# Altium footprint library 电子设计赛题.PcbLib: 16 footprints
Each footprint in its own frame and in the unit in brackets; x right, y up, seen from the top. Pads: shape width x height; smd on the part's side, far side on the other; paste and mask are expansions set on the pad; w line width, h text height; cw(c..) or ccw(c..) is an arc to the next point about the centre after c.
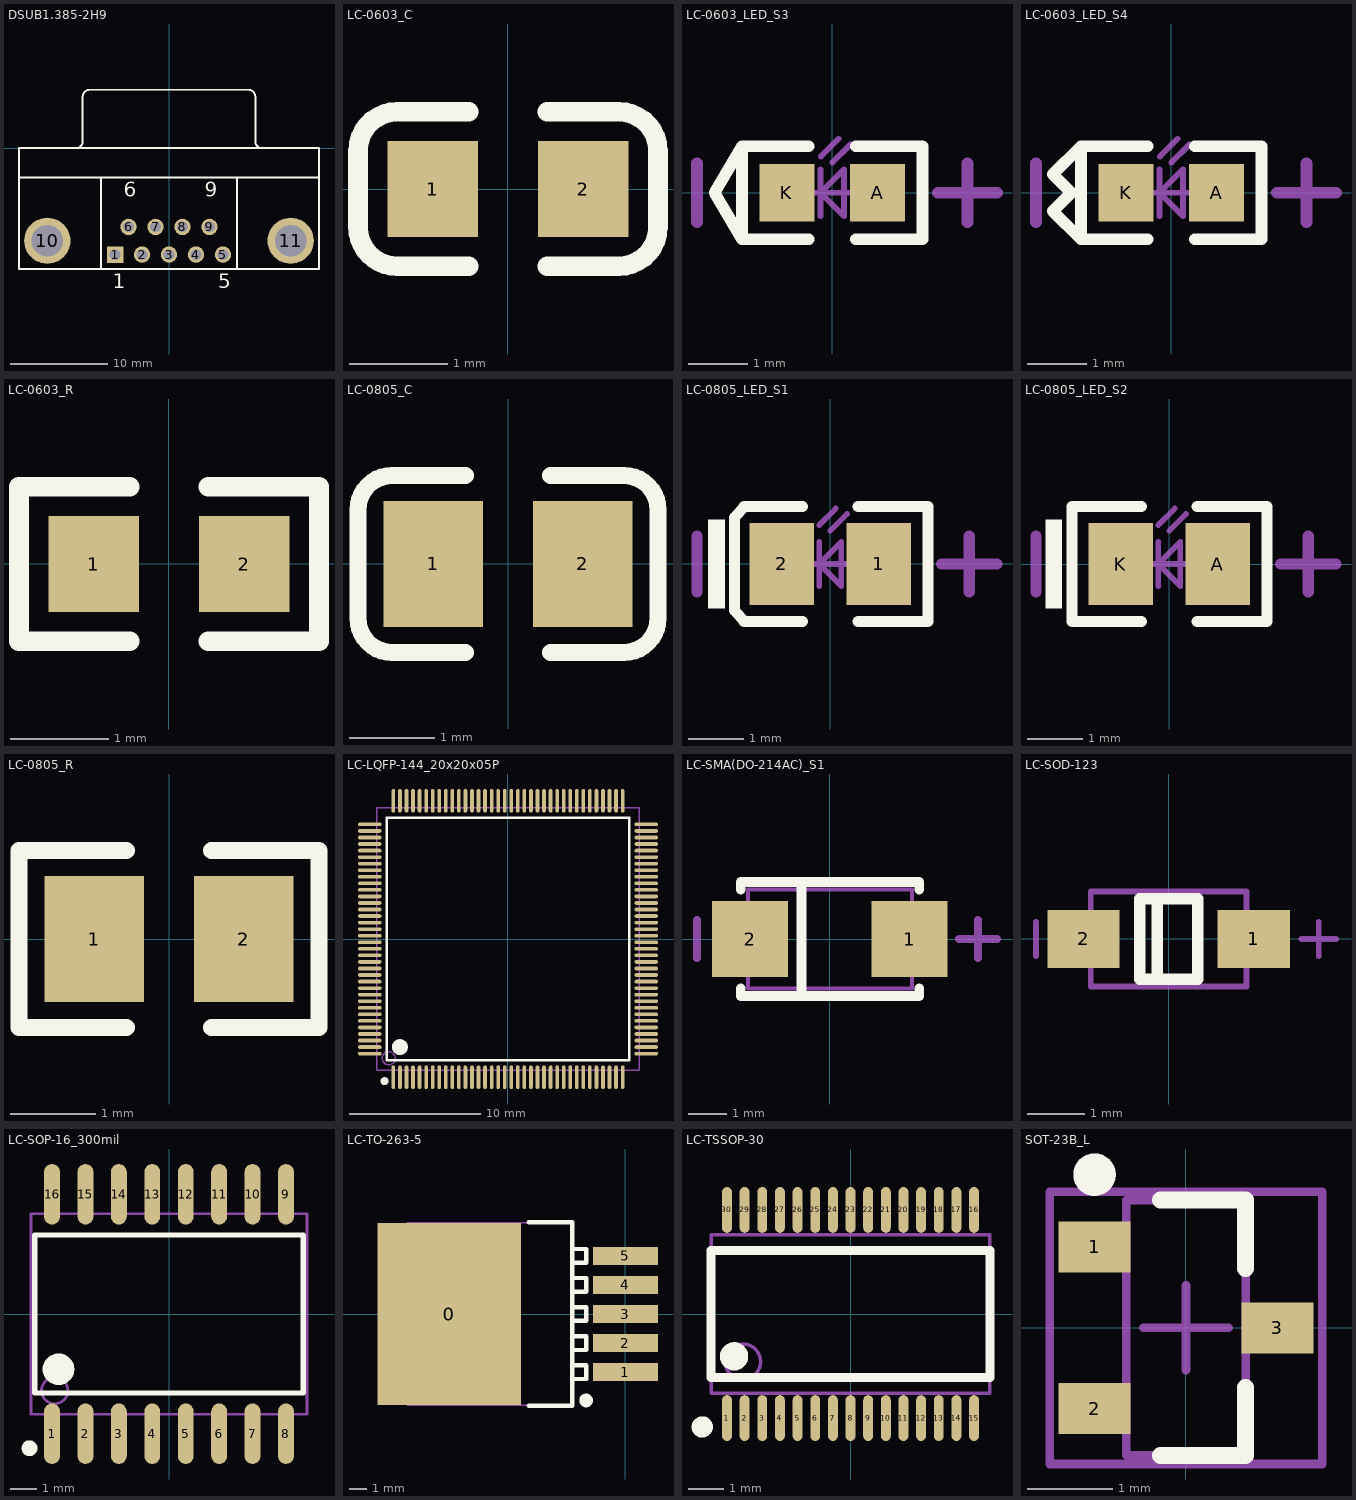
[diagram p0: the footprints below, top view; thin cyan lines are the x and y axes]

## DSUB1.385-2H9 [mm] "Connector; D Subminiature; 9 Position; Right Angle; Pitch 1.385 mm"
height 12.75
pads (11):
  rect 1.69x1.69 hole 1.09: 1(-5.54,-10.92)
  round 1.69 hole 1.09: 2(-2.77,-10.92) 3(0,-10.92) 4(2.77,-10.92) 5(5.54,-10.92) 6(-4.155,-8.08) 7(-1.385,-8.08) 8(1.385,-8.08) 9(4.155,-8.08)
  round 4.76 hole 3.26: 10(-12.495,-9.5) 11(12.495,-9.5)
Top Overlay:
  lines w0.2: -15.4,-3 15.4,-3 ; -9.56,0.005 ccw(c-9.56,0.7) -8.865,0.7 -8.865,5.3 ; -8.86,5.305 cw(c-8.165,5.305) -8.165,6 8.165,6 cw(c8.165,5.305) 8.86,5.305 ; -7,-12.4 -7,-3 ; 7,-12.4 7,-3 ; 8.865,5.3 8.865,0.7 ccw(c9.56,0.7) 9.56,0.005 ; -15.4,-12.4 15.4,-12.4 15.4,0 -15.4,0 -15.4,-12.4
  text "6" at -4.655,-4.975 h1.5
  text "9" at 3.655,-4.975 h1.5
  text "5" at 5.04,-14.375 h1.5
  text "1" at -5.79,-14.375 h1.5

## LC-0603_C [mm]
height 1.1
pads (2):
  rect 0.93x0.98 smd: 1(-0.77,0) 2(0.77,0)
Top Overlay:
  lines w0.2: -0.4,-0.79 -1.135,-0.79 cw(c-1.135,-0.39) -1.535,-0.39 -1.535,0.39 cw(c-1.135,0.39) -1.135,0.79 -0.4,0.79 ; 0.4,-0.79 1.135,-0.79 ccw(c1.135,-0.39) 1.535,-0.39 1.535,0.39 ccw(c1.135,0.39) 1.135,0.79 0.4,0.79
3D body "User Library-0603 SMD Capacitor.STEP": height 0.3, standoff 0, extent -0.8,-0.4 0.8,0.4

## LC-0603_LED_S3 [mm]
height 1.1
pads (2):
  rect 0.93x0.98 smd: A(0.77,0) K(-0.77,0)
Top Overlay:
  lines w0.2: -0.4,-0.79 -1.535,-0.79 ; -0.4,0.79 -1.535,0.79 ; 0.4,-0.79 1.535,-0.79 1.535,0.79 0.4,0.79 ; -1.535,-0.79 -2,0 -1.535,0.79 ; -1.535,-0.79 -1.535,0.79
Mechanical 13:
  lines w0.1: -0.4,0 0.4,0 ; -0.2,-0.4 -0.2,0.4 ; -0.195,0.617 0.105,0.917 ; 0.005,0.517 0.305,0.817 ; -0.2,0 0.2,0.4 0.2,-0.4 -0.2,0
Mechanical 15:
  lines w0.203: -2.3,-0.5 -2.3,0.5 ; 1.8,0 2.8,0 ; 2.3,-0.5 2.3,0.5
3D body "User Library-LED_0603_R.STEP": height 0.6, standoff 0, extent -0.8,-0.4 0.8,0.4

## LC-0603_LED_S4 [mm]
height 1.1
pads (2):
  rect 0.93x0.98 smd: A(0.77,0) K(-0.77,0)
Top Overlay:
  lines w0.2: -0.4,-0.79 -1.535,-0.79 ; -0.4,0.79 -1.535,0.79 ; 0.4,-0.79 1.535,-0.79 1.535,0.79 0.4,0.79 ; -1.535,-0.79 -2.012,-0.313 -1.7,0 -2.012,0.313 -1.535,0.79 ; -1.535,-0.79 -1.535,0.79
Mechanical 13:
  lines w0.1: -0.4,0 0.4,0 ; -0.2,-0.4 -0.2,0.4 ; -0.195,0.617 0.105,0.917 ; 0.005,0.517 0.305,0.817 ; -0.2,0 0.2,-0.4 0.2,0.4 -0.2,0
Mechanical 15:
  lines w0.203: -2.3,-0.5 -2.3,0.5 ; 1.8,0 2.8,0 ; 2.3,-0.5 2.3,0.5
3D body "User Library-LED_0603_R.STEP": height 0.6, standoff 0, extent -0.8,-0.4 0.8,0.4

## LC-0603_R [mm]
height 1.1
pads (2):
  rect 0.93x0.98 smd: 1(-0.77,0) 2(0.77,0)
Top Overlay:
  lines w0.2: -0.4,-0.79 -1.535,-0.79 -1.535,0.79 -0.4,0.79 ; 0.4,-0.79 1.535,-0.79 1.535,0.79 0.4,0.79
3D body "User Library-RES_1609-0603.STEP": height 0.56, standoff 0, extent -0.85,-0.4 0.85,0.4

## LC-0805_C [mm]
height 1.1
pads (2):
  rect 1.16x1.47 smd: 1(-0.875,0) 2(0.875,0)
Top Overlay:
  lines w0.2: -0.5,-1.035 -1.355,-1.035 cw(c-1.355,-0.635) -1.755,-0.635 -1.755,0.635 cw(c-1.355,0.635) -1.355,1.035 -0.5,1.035 ; 0.5,-1.035 1.355,-1.035 ccw(c1.355,-0.635) 1.755,-0.635 1.755,0.635 ccw(c1.355,0.635) 1.355,1.035 0.5,1.035
3D body "User Library-0805 SMD Capacitor.STEP": height 0.77, standoff -0.01, extent -0.999,-0.625 1.001,0.625

## LC-0805_LED_S1 [mm]
height 1.1
pads (2):
  rect 1.16x1.47 smd: 1(0.875,0) 2(-0.875,0)
Top Overlay:
  rectangle: -2.2,-0.8 -1.9,0.8
  lines w0.2: -0.5,-1.035 -1.55,-1.035 -1.725,-0.835 -1.725,0.835 -1.55,1.035 -0.5,1.035 ; 0.5,-1.035 1.755,-1.035 1.755,1.035 0.5,1.035
Mechanical 13:
  lines w0.1: -0.4,0 0.4,0 ; -0.2,-0.4 -0.2,0.4 ; -0.2,0.7 0.1,1 ; 0,0.6 0.3,0.9 ; -0.2,0 0.2,-0.4 0.2,0.4 -0.2,0
Mechanical 15:
  lines w0.203: -2.4,-0.5 -2.4,0.5 ; 2,0 3,0 ; 2.5,-0.5 2.5,0.5
3D body "User Library-led_0805.step": height 1.1, standoff 0, extent -1.01,-0.625 1.01,0.625

## LC-0805_LED_S2 [mm]
height 1.1
pads (2):
  rect 1.16x1.47 smd: A(0.875,0) K(-0.875,0)
Top Overlay:
  rectangle: -2.23,-0.8 -1.93,0.8
  lines w0.2: -0.5,-1.035 -1.755,-1.035 -1.755,1.035 -0.5,1.035 ; 0.5,-1.035 1.755,-1.035 1.755,1.035 0.5,1.035
Mechanical 13:
  lines w0.1: -0.4,0 0.4,0 ; -0.2,-0.4 -0.2,0.4 ; -0.2,0.7 0.1,1 ; 0,0.6 0.3,0.9 ; -0.2,0 0.2,-0.4 0.2,0.4 -0.2,0
Mechanical 15:
  lines w0.203: -2.4,-0.5 -2.4,0.5 ; 2,0 3,0 ; 2.5,-0.5 2.5,0.5
3D body "User Library-led_0805.step": height 1.1, standoff 0, extent -1.01,-0.625 1.01,0.625

## LC-0805_R [mm]
height 1.1
pads (2):
  rect 1.16x1.47 smd: 1(-0.875,0) 2(0.875,0)
Top Overlay:
  lines w0.2: -0.5,-1.035 -1.755,-1.035 -1.755,1.035 -0.5,1.035 ; 0.5,-1.035 1.755,-1.035 1.755,1.035 0.5,1.035
3D body "User Library-R_0805.STEP": height 0.49, standoff -0.01, extent -0.997,-0.625 1.003,0.625

## LC-LQFP-144_20x20x05P [mm]
height 1.1
pads (144):
  oval 0.28x1.8 smd mask+0.051: 1(-8.75,-10.55) 2(-8.25,-10.55) 3(-7.75,-10.55) 4(-7.25,-10.55) 5(-6.75,-10.55) 6(-6.25,-10.55) 7(-5.75,-10.55) 8(-5.25,-10.55) 9(-4.75,-10.55) 10(-4.25,-10.55) 11(-3.75,-10.55) 12(-3.25,-10.55) 13(-2.75,-10.55) 14(-2.25,-10.55) 15(-1.75,-10.55) 16(-1.25,-10.55) 17(-0.75,-10.55) 18(-0.25,-10.55) 19(0.25,-10.55) 20(0.75,-10.55) 21(1.25,-10.55) 22(1.75,-10.55) 23(2.25,-10.55) 24(2.75,-10.55) 25(3.25,-10.55) 26(3.75,-10.55) 27(4.25,-10.55) 28(4.75,-10.55) 29(5.25,-10.55) 30(5.75,-10.55) 31(6.25,-10.55) 32(6.75,-10.55) 33(7.25,-10.55) 34(7.75,-10.55) 35(8.25,-10.55) 36(8.75,-10.55) 73(8.75,10.55) 74(8.25,10.55) 75(7.75,10.55) 76(7.25,10.55) 77(6.75,10.55) 78(6.25,10.55) 79(5.75,10.55) 80(5.25,10.55) 81(4.75,10.55) 82(4.25,10.55) 83(3.75,10.55) 84(3.25,10.55) 85(2.75,10.55) 86(2.25,10.55) 87(1.75,10.55) 88(1.25,10.55) 89(0.75,10.55) 90(0.25,10.55) 91(-0.25,10.55) 92(-0.75,10.55) 93(-1.25,10.55) 94(-1.75,10.55) 95(-2.25,10.55) 96(-2.75,10.55) 97(-3.25,10.55) 98(-3.75,10.55) 99(-4.25,10.55) 100(-4.75,10.55) 101(-5.25,10.55) 102(-5.75,10.55) 103(-6.25,10.55) 104(-6.75,10.55) 105(-7.25,10.55) 106(-7.75,10.55) 107(-8.25,10.55) 108(-8.75,10.55)
  oval 1.8x0.28 smd mask+0.051: 37(10.55,-8.75) 38(10.55,-8.25) 39(10.55,-7.75) 40(10.55,-7.25) 41(10.55,-6.75) 42(10.55,-6.25) 43(10.55,-5.75) 44(10.55,-5.25) 45(10.55,-4.75) 46(10.55,-4.25) 47(10.55,-3.75) 48(10.55,-3.25) 49(10.55,-2.75) 50(10.55,-2.25) 51(10.55,-1.75) 52(10.55,-1.25) 53(10.55,-0.75) 54(10.55,-0.25) 55(10.55,0.25) 56(10.55,0.75) 57(10.55,1.25) 58(10.55,1.75) 59(10.55,2.25) 60(10.55,2.75) 61(10.55,3.25) 62(10.55,3.75) 63(10.55,4.25) 64(10.55,4.75) 65(10.55,5.25) 66(10.55,5.75) 67(10.55,6.25) 68(10.55,6.75) 69(10.55,7.25) 70(10.55,7.75) 71(10.55,8.25) 72(10.55,8.75) 109(-10.55,8.75) 110(-10.55,8.25) 111(-10.55,7.75) 112(-10.55,7.25) 113(-10.55,6.75) 114(-10.55,6.25) 115(-10.55,5.75) 116(-10.55,5.25) 117(-10.55,4.75) 118(-10.55,4.25) 119(-10.55,3.75) 120(-10.55,3.25) 121(-10.55,2.75) 122(-10.55,2.25) 123(-10.55,1.75) 124(-10.55,1.25) 125(-10.55,0.75) 126(-10.55,0.25) 127(-10.55,-0.25) 128(-10.55,-0.75) 129(-10.55,-1.25) 130(-10.55,-1.75) 131(-10.55,-2.25) 132(-10.55,-2.75) 133(-10.55,-3.25) 134(-10.55,-3.75) 135(-10.55,-4.25) 136(-10.55,-4.75) 137(-10.55,-5.25) 138(-10.55,-5.75) 139(-10.55,-6.25) 140(-10.55,-6.75) 141(-10.55,-7.25) 142(-10.55,-7.75) 143(-10.55,-8.25) 144(-10.55,-8.75)
Top Overlay:
  circle w0.3: c-9.425,-10.85 r0.15
  circle w0.6: c-8.25,-8.25 r0.3
  lines w0.2: -9.25,-9.25 -9.25,9.25 9.25,9.25 9.25,-9.25 -9.25,-9.25
Mechanical 13:
  circle w0.1: c-9.1,-9.1 r0.5
  lines w0.1: -10,-10 -10,10 10,10 10,-10 -10,-10

## LC-SMA(DO-214AC)_S1 [mm]
height 1.1
pads (2):
  rect 2x2 smd: 1(2.1,0) 2(-2.1,0)
Top Overlay:
  lines w0.254: -2.35,-1.3 -2.35,-1.5 2.35,-1.5 2.35,-1.3 ; -2.35,1.3 -2.35,1.5 2.35,1.5 2.35,1.3 ; -0.75,-1.5 -0.75,1.5
Mechanical 13:
  lines w0.1: -2.16,-1.3 -2.16,1.3 2.16,1.3 2.16,-1.3 -2.16,-1.3
Mechanical 15:
  lines w0.203: -3.5,-0.5 -3.5,0.5 ; 3.4,0 4.4,0 ; 3.9,-0.5 3.9,0.5

## LC-SOD-123 [mm]
height 1.1
pads (2):
  rect 1.25x1 smd: 1(1.475,0) 2(-1.475,0)
Top Overlay:
  lines w0.2: -0.2,-0.7 -0.2,0.7 ; -0.5,-0.7 0.5,-0.7 0.5,0.7 -0.5,0.7 -0.5,-0.7
Mechanical 13:
  lines w0.1: -1.35,-0.825 -1.35,0.825 1.35,0.825 1.35,-0.825 -1.35,-0.825
Mechanical 15:
  lines w0.1: -2.3,-0.3 -2.3,0.3 ; 2.3,0 2.9,0 ; 2.6,-0.3 2.6,0.3
3D body "SOD123.STEP": height 1.35, standoff 0, extent -1.85,-0.775 1.85,0.775

## LC-SOP-16_300mil [mm]
height 1.1
pads (16):
  oval 0.6x2.3 smd: 1(-4.445,-4.55) 2(-3.175,-4.55) 3(-1.905,-4.55) 4(-0.635,-4.55) 5(0.635,-4.55) 6(1.905,-4.55) 7(3.175,-4.55) 8(4.445,-4.55) 9(4.445,4.55) 10(3.175,4.55) 11(1.905,4.55) 12(0.635,4.55) 13(-0.635,4.55) 14(-1.905,4.55) 15(-3.175,4.55) 16(-4.445,4.55)
Top Overlay:
  circle w0.3: c-5.3,-5.1 r0.15
  circle w0.6: c-4.2,-2.1 r0.3
  lines w0.2: -5.1,-3 -5.1,3 5.1,3 5.1,-3 -5.1,-3
Mechanical 13:
  circle w0.1: c-4.345,-2.91 r0.5
  lines w0.1: -5.245,-3.81 -5.245,3.81 5.245,3.81 5.245,-3.81 -5.245,-3.81

## LC-TO-263-5 [mm]
height 1.1
pads (6):
  rect 8.4x10.65 smd: 0(-10.3,0)
  rect 3.8x1.05 smd: 1(0,-3.4) 2(0,-1.7) 3(0,0) 4(0,1.7) 5(0,3.4)
Top Overlay:
  circle w0.4: c-2.3,-5.05 r0.2
  lines w0.254: -5.65,-5.35 -3.1,-5.35 -3.1,5.35 -5.65,5.35 ; -3.1,-3 -2.3,-3 -2.3,-3.8 -3,-3.8 ; -3.1,-1.3 -2.3,-1.3 -2.3,-2.1 -3,-2.1 ; -3.1,0.4 -2.3,0.4 -2.3,-0.4 -3,-0.4 ; -3.1,2.1 -2.3,2.1 -2.3,1.3 -3,1.3 ; -3.1,3.8 -2.3,3.8 -2.3,3 -3,3
Mechanical 13:
  lines w0.1: -12.75,-5.325 -12.75,5.325 -3.1,5.325 -3.1,-5.325 -12.75,-5.325

## LC-TSSOP-30 [mm]
height 1.1
pads (30):
  oval 0.28x1.3 smd mask+0.051: 1(-3.5,-2.95) 2(-3,-2.95) 3(-2.5,-2.95) 4(-2,-2.95) 5(-1.5,-2.95) 6(-1,-2.95) 7(-0.5,-2.95) 8(0,-2.95) 9(0.5,-2.95) 10(1,-2.95) 11(1.5,-2.95) 12(2,-2.95) 13(2.5,-2.95) 14(3,-2.95) 15(3.5,-2.95) 16(3.5,2.95) 17(3,2.95) 18(2.5,2.95) 19(2,2.95) 20(1.5,2.95) 21(1,2.95) 22(0.5,2.95) 23(0,2.95) 24(-0.5,2.95) 25(-1,2.95) 26(-1.5,2.95) 27(-2,2.95) 28(-2.5,2.95) 29(-3,2.95) 30(-3.5,2.95)
Top Overlay:
  circle w0.3: c-4.2,-3.2 r0.15
  circle w0.4: c-3.3,-1.2 r0.2
  lines w0.254: -3.95,-1.8 -3.95,1.8 3.95,1.8 3.95,-1.8 -3.95,-1.8
Mechanical 13:
  circle w0.1: c-3.05,-1.35 r0.5
  lines w0.1: -3.95,-2.25 -3.95,2.25 3.95,2.25 3.95,-2.25 -3.95,-2.25

## SOT-23B_L [mm] "SOT23, 3-Leads, Body 2.9x1.3mm, Pitch 0.95mm, Lead Span 2.4mm, IPC High Density"
height 1.14
pads (3):
  rect 0.85x0.6 smd: 1(-1.075,0.95) 2(-1.075,-0.95) 3(1.075,0)
Top Overlay:
  circle w0.25: c-1.075,1.8 r0.125
  lines w0.2: -0.3,-1.5 0.7,-1.5 0.7,-0.7 ; -0.3,1.5 0.7,1.5 0.7,0.7
Mechanical 13:
  lines w0.1: -0.7,-1.5 -0.7,1.5 0.7,1.5 0.7,-1.5 -0.7,-1.5
Mechanical 15:
  lines w0.1: -0.5,0 0.5,0 ; 0,-0.5 0,0.5 ; -1.6,-1.6 -1.6,1.6 1.6,1.6 1.6,-1.6 -1.6,-1.6
3D body: height 1.14, standoff 0, extent -0.7,-1.5 0.7,1.5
